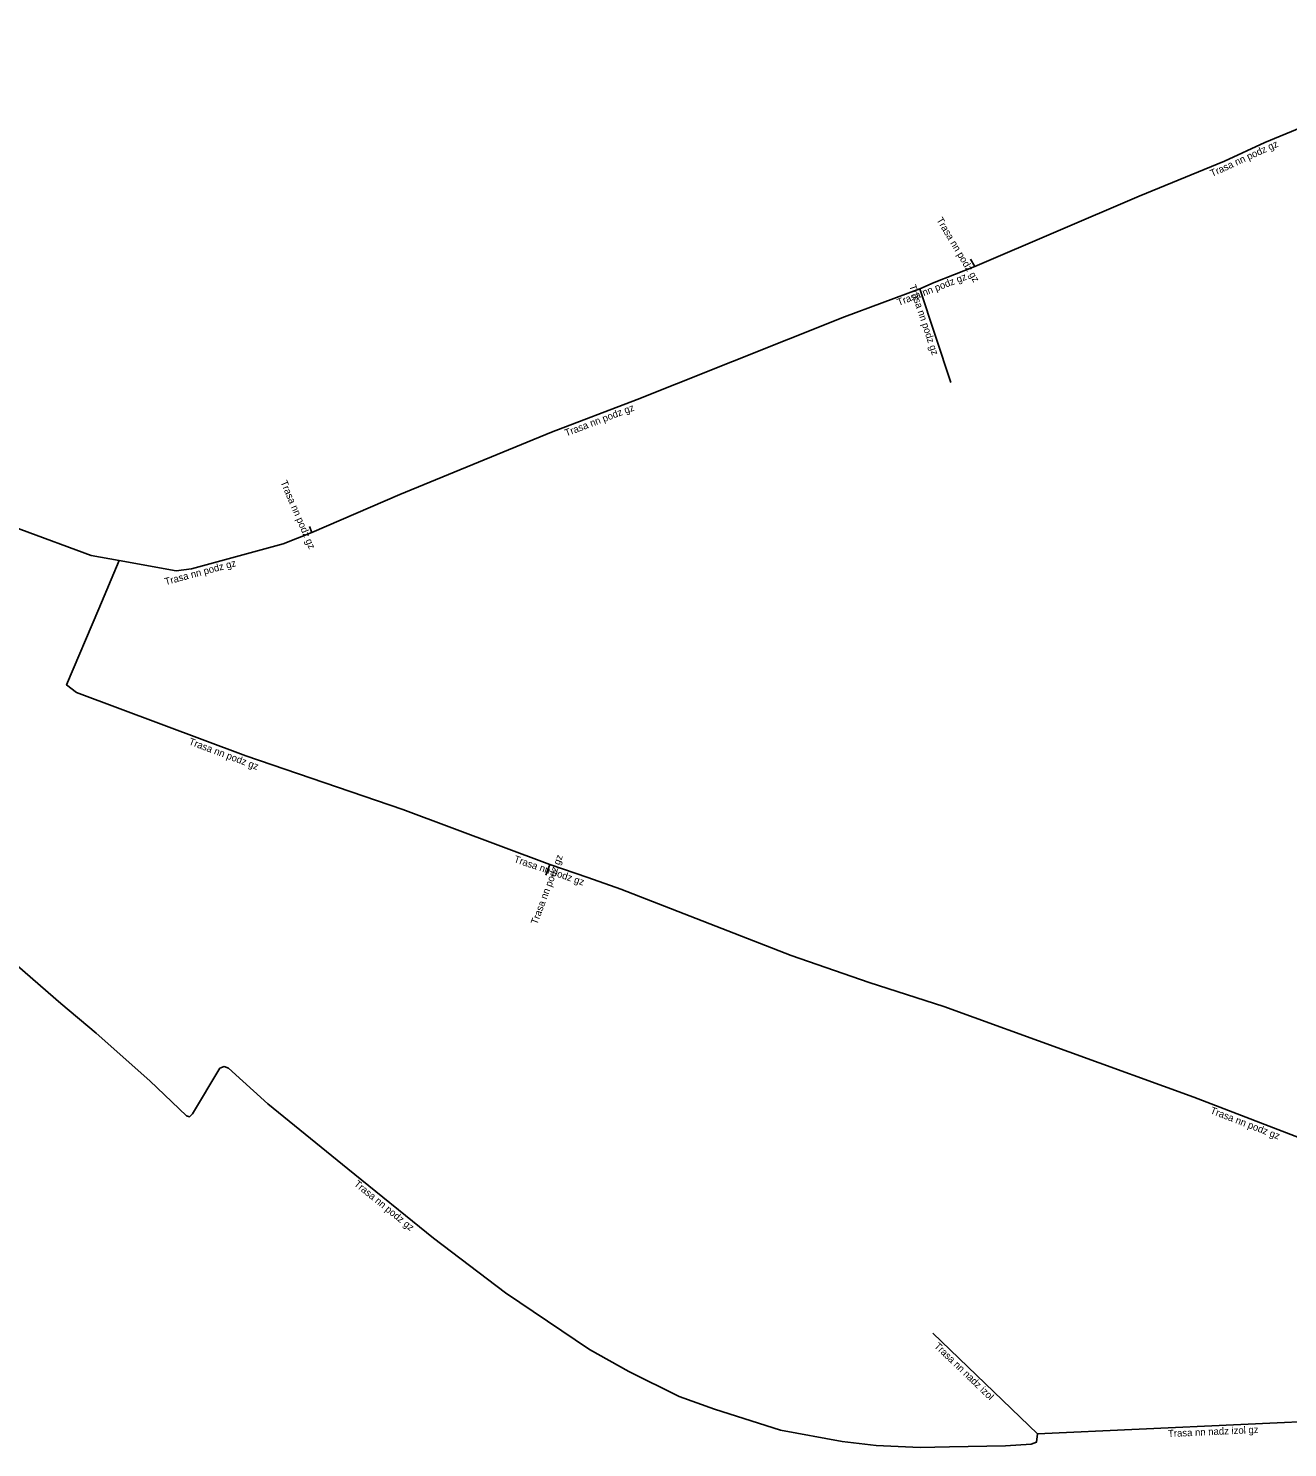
# Model space of a CAD drawing. Extents: x -748073 to -746986, y -1069233 to -1068700.
# Drawn here: x -747847.4 to -747759, y -1068944.9 to -1068845.4 of the extents above; entities that cross this region are included whole.
import ezdxf

# ---------------------------------------------------------------- set-up
doc = ezdxf.new("R2010")
doc.units = 0
doc.layers.add('Popiskový text - Ostatní atributy Trasy', color=7, linetype='Continuous')
doc.layers.add('Spojnice NN', color=7, linetype='Continuous')

msp = doc.modelspace()

# ---------------------------------------------------------------- linework, layer by layer
at = {"layer": 'Spojnice NN'}
for points in [[(-747781.01, -1068862.08), (-747769.46, -1068857.14), (-747763.47, -1068854.68), (-747760.64, -1068853.38), (-747748.96, -1068848.57), (-747742.84, -1068846.11), (-747741.04, -1068845.37)], [(-747781.01, -1068862.08), (-747781.32, -1068861.56)], [(-747784.87, -1068863.65), (-747783.87, -1068863.19), (-747781.01, -1068862.08)], [(-747883.43, -1068863.83), (-747884.13, -1068864.62), (-747883.68, -1068867.21), (-747874.12, -1068870.84), (-747857.88, -1068876.88), (-747843.04, -1068882.36), (-747841.08, -1068882.71)], [(-747827.54, -1068880.74), (-747821.38, -1068878.08), (-747810.72, -1068873.71), (-747804.7, -1068871.41), (-747801.94, -1068870.31), (-747790.16, -1068865.62), (-747784.87, -1068863.65)], [(-747784.87, -1068863.65), (-747782.69, -1068870.21)], [(-747841.08, -1068882.71), (-747837.07, -1068883.43), (-747836, -1068883.28), (-747829.57, -1068881.54), (-747827.54, -1068880.74)], [(-747827.54, -1068880.74), (-747827.72, -1068880.32)], [(-747841.08, -1068882.71), (-747842.51, -1068886.1), (-747844.76, -1068891.44), (-747844.07, -1068891.97), (-747832.19, -1068896.42), (-747821.16, -1068900.18), (-747810.835, -1068904.046)], [(-747811.111, -1068904.783), (-747810.835, -1068904.046)], [(-747810.835, -1068904.046), (-747808.181, -1068904.949)], [(-747808.181, -1068904.949), (-747805.86, -1068905.77), (-747793.91, -1068910.42), (-747788.43, -1068912.31), (-747783.17, -1068913.99), (-747765.62, -1068920.36), (-747757.3, -1068923.57), (-747744.93, -1068928.08), (-747732.43, -1068932.13), (-747729, -1068933), (-747721.6, -1068933.73), (-747713.2, -1068934.3), (-747713.14, -1068935.09), (-747713.41, -1068935.52)], [(-747776.602, -1068943.979), (-747776.67, -1068944.56), (-747777.06, -1068944.71), (-747778.86, -1068944.83), (-747782.78, -1068944.9), (-747784.84, -1068944.95), (-747787.92, -1068944.79), (-747790.31, -1068944.53), (-747794.64, -1068943.73), (-747799.28, -1068942.25), (-747801.77, -1068941.37), (-747805.29, -1068939.62), (-747808.05, -1068938.07), (-747813.96, -1068934.08), (-747819, -1068930.26), (-747825.01, -1068925.38), (-747830.64, -1068920.82), (-747833.4, -1068918.32), (-747833.7, -1068918.21), (-747834, -1068918.33), (-747835.92, -1068921.54), (-747836.14, -1068921.73), (-747836.35, -1068921.68), (-747838.93, -1068919.21), (-747842.69, -1068915.87), (-747845.16, -1068913.78), (-747848.21, -1068911.15)], [(-747776.602, -1068943.979), (-747783.964, -1068936.909)], [(-747748.06, -1068942.68), (-747776.602, -1068943.979)]]:
    msp.add_lwpolyline(points, dxfattribs=at)

# ---------------------------------------------------------------- texts
at = {"layer": 'Popiskový text - Ostatní atributy Trasy'}
for s, rotation, p in [('Trasa nn podz gz', 24.67234, (-747764.351, -1068855.801)), ('Trasa nn podz gz', 300.80145, (-747783.718, -1068858.809)), ('Trasa nn podz gz', 21.21182, (-747786.347, -1068864.849)), ('Trasa nn podz gz', 288.38253, (-747785.625, -1068863.44)), ('Trasa nn podz gz', 20.90985, (-747809.684, -1068874.01)), ('Trasa nn podz gz', 293.19859, (-747829.762, -1068877.208)), ('Trasa nn podz gz', 15.14196, (-747837.808, -1068884.442)), ('Trasa nn podz gz', 339.4651, (-747836.229, -1068895.601)), ('Trasa nn podz gz', 341.20958, (-747813.404, -1068903.858)), ('Trasa nn podz gz', 69.46952, (-747811.729, -1068908.289)), ('Trasa nn podz gz', 338.90252, (-747764.522, -1068921.481)), ('Trasa nn podz gz', 320.92409, (-747824.628, -1068926.527)), ('Trasa nn nadz izol', 316.1591, (-747783.899, -1068937.873)), ('Trasa nn nadz izol gz', 2.60584, (-747767.432, -1068944.212))]:
    msp.add_text(s, height=0.5, rotation=rotation, dxfattribs=at).set_placement(p)

doc.saveas('drawing.dxf')
